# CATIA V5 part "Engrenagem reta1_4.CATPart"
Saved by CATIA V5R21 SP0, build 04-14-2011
Part number: Engrenagem reta1_4
Definition: Engrenagem reta1_4
Nomenclature: Engrenagem reta18
Source: Unknown
Bounding box of the stored display mesh (mm): x -0.99 to 0.99, y -0.989 to 0.989, z 0 to 1.75
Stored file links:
  C:\Users\beatr\OneDrive\Documents\UNB\2026_1\Pi1\Componentes eletronicos\Engrenagem reta1_4.CATPart
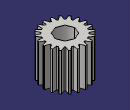
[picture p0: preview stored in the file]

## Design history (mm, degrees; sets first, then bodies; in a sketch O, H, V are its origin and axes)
Body1 "Solid1" (main body)
  Solid1: solid without history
